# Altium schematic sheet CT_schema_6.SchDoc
size 369 x 333 mm
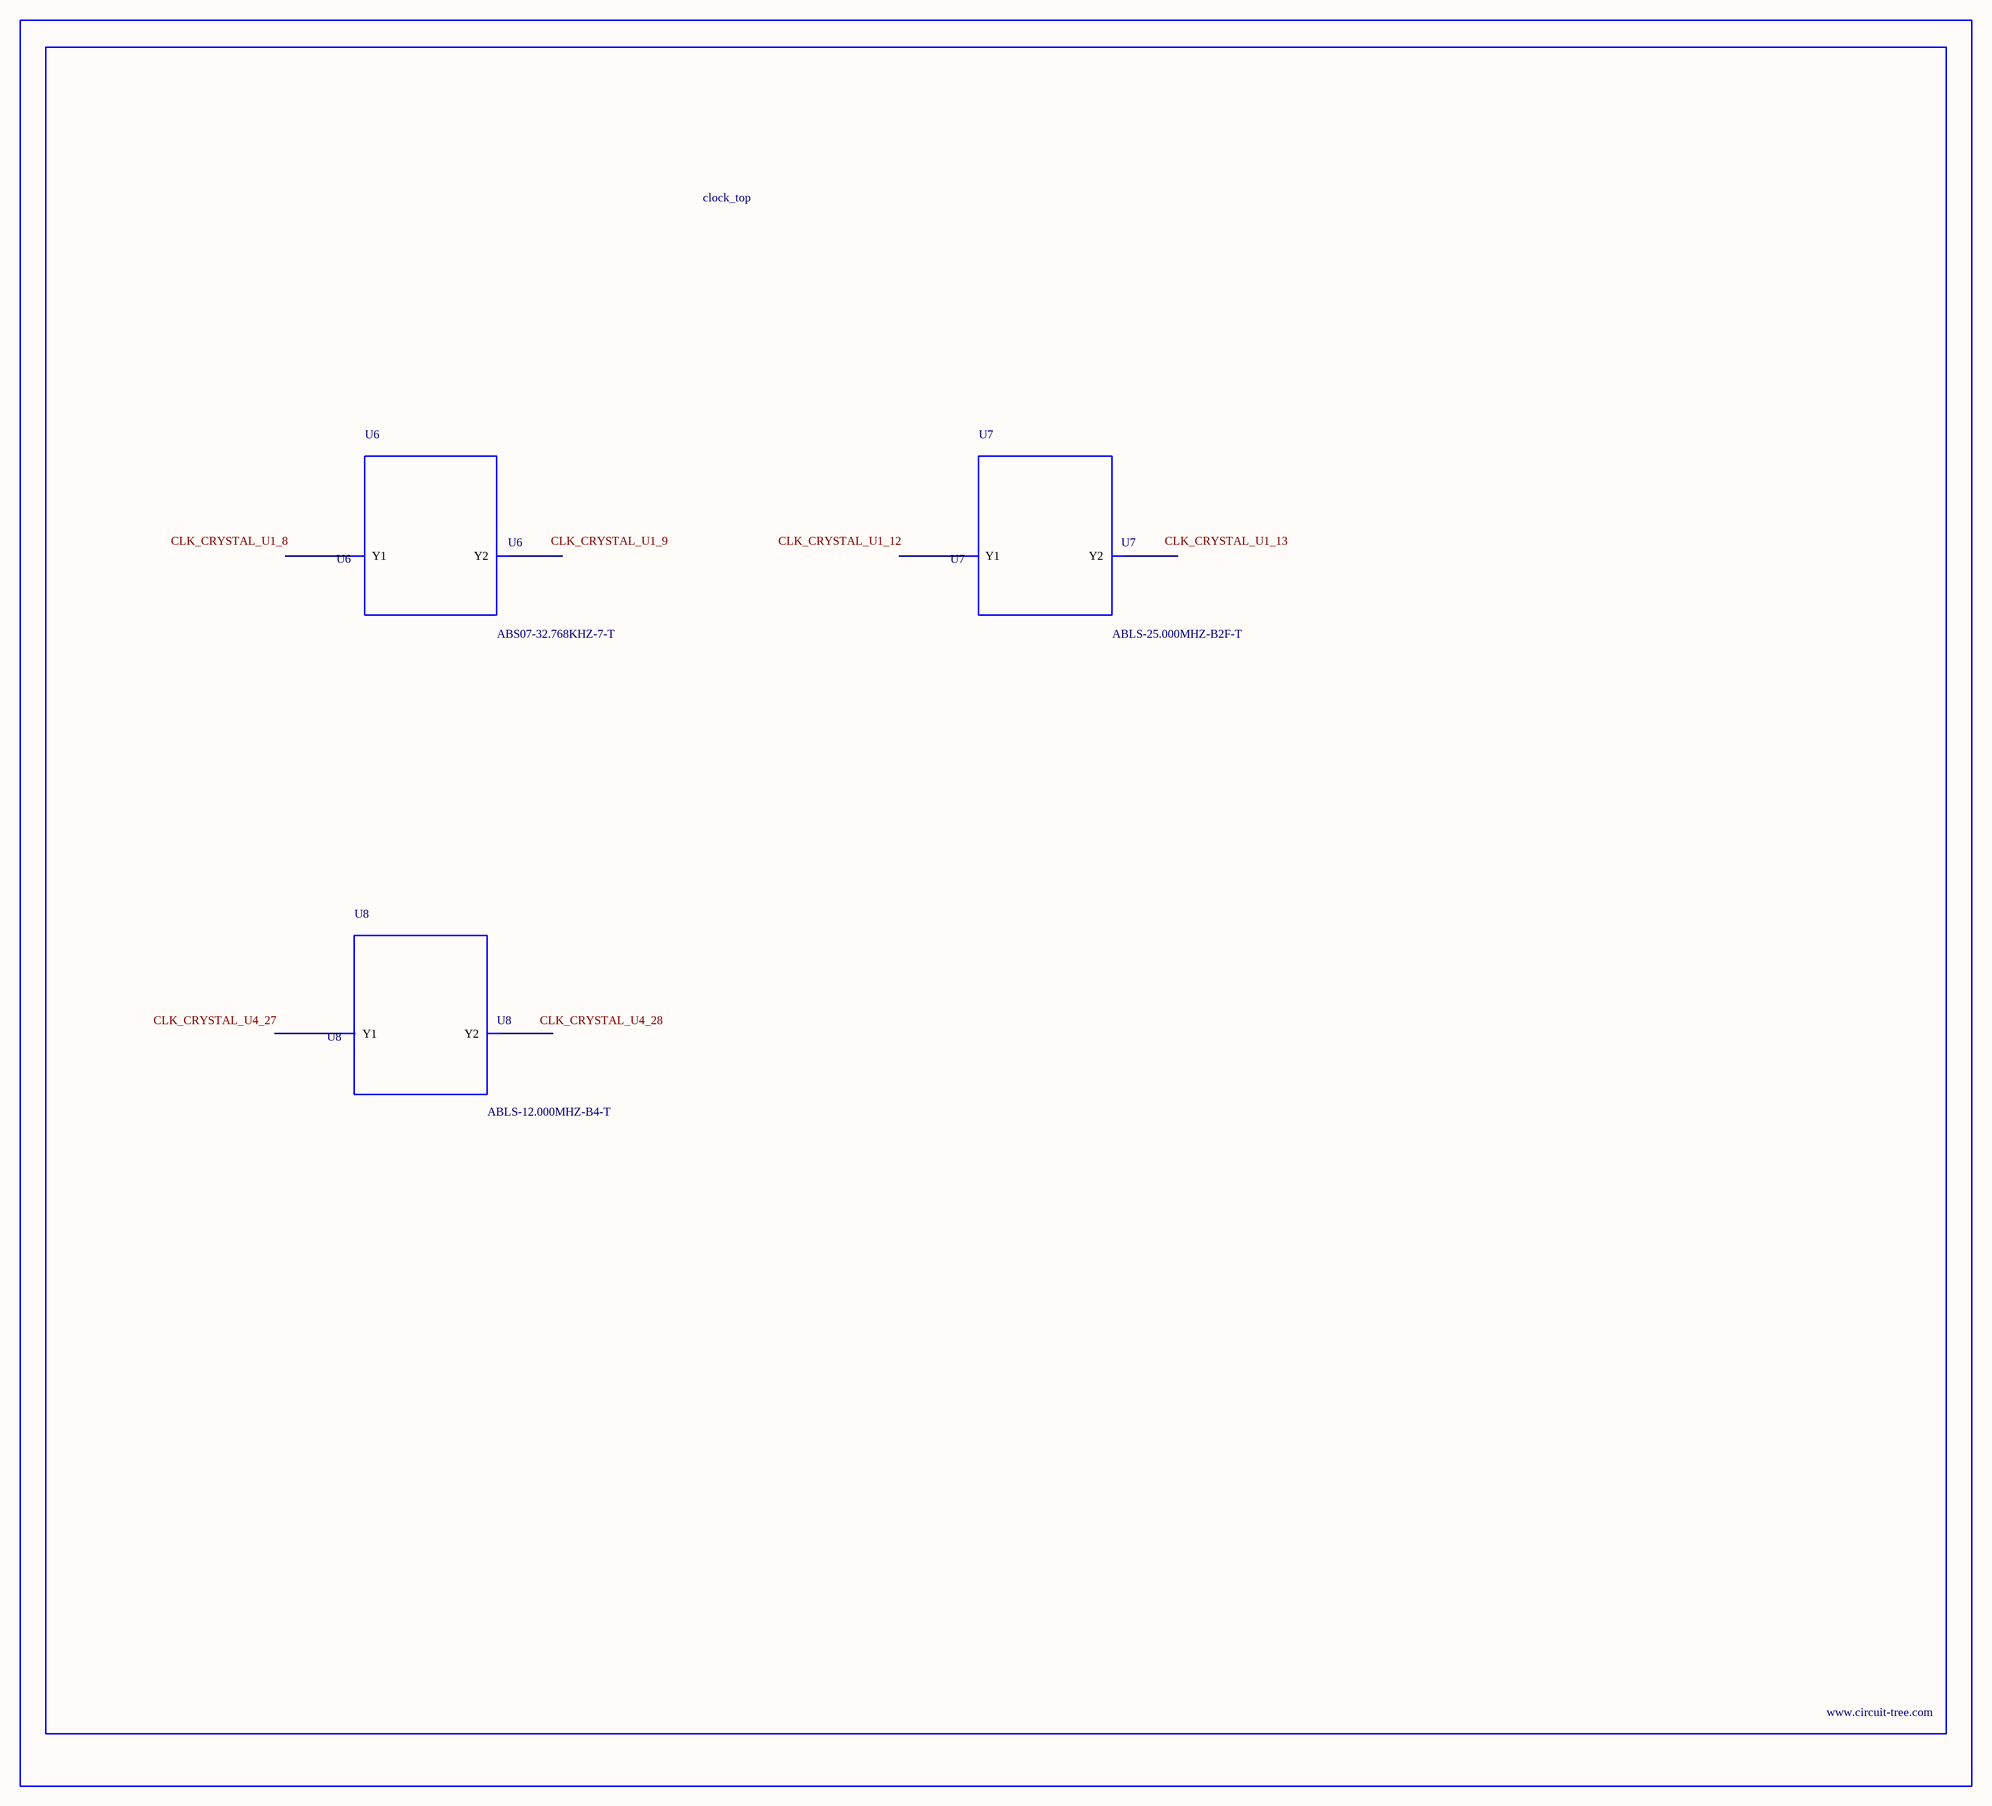
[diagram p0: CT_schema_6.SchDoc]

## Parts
BORDER5  (no value)
U6  ABS07-32.768KHZ-7-T  [ABS07-32.768KHZ-7-T]
U7  ABLS-25.000MHZ-B2F-T  [ABLS-25.000MHZ-B2F-T]
U8  ABLS-12.000MHZ-B4-T  [ABLS-12.000MHZ-B4-T]

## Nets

Not connected (* = marked no-connect by the designer): U6 1(Y1) 2(Y2); U7 1(Y1) 2(Y2); U8 1(Y1) 2(Y2)

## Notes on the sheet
- Labels drawn without touching a wire or pin: CLK_CRYSTAL_U1_8, CLK_CRYSTAL_U1_9, CLK_CRYSTAL_U1_12, CLK_CRYSTAL_U1_13, CLK_CRYSTAL_U4_27, CLK_CRYSTAL_U4_28

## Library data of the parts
BORDER5 = BORDER_PAGE5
